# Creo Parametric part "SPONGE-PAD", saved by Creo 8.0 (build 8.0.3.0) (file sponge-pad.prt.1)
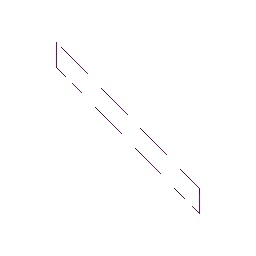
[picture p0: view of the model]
Units: millimeter Newton Second (mmNs); MM, TONNE, SECS

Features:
  1. datum plane "DTM1"
  2. datum plane "DTM2"
  3. protrusion
  4. cut
  5. datum plane "DTM3"
  6. cut

Layers: 0_ALL_AXIS, 0_ALL_CSYS, 0_ALL_CURVES, 0_ALL_PLANES, 0_ALL_POINTS, 0_ALL_SURFS, SPONGE-PAD

Surfaces: 5 plane, 4 cylinder, 4 torus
